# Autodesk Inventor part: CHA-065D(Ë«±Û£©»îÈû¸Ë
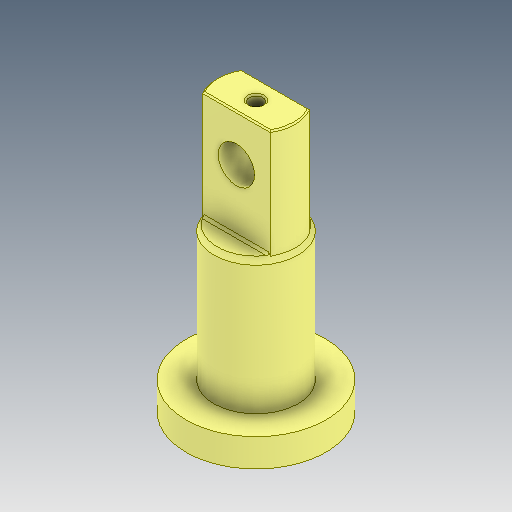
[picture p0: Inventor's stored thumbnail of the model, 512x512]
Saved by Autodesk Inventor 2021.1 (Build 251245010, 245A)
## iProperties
Created: 2021-05
Part Number: CHA-065D(Ë«±Û£©»îÈû¸Ë
Material: Ogólny
Document SubType Name: Modeling
Designer: user
Density: 1 g/cm^3
Appearance: Domyślna
Author: user
Revision Number: ÈÎºÎ
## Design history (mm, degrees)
feature "ÊäÈë1"
node "Bryła1"
